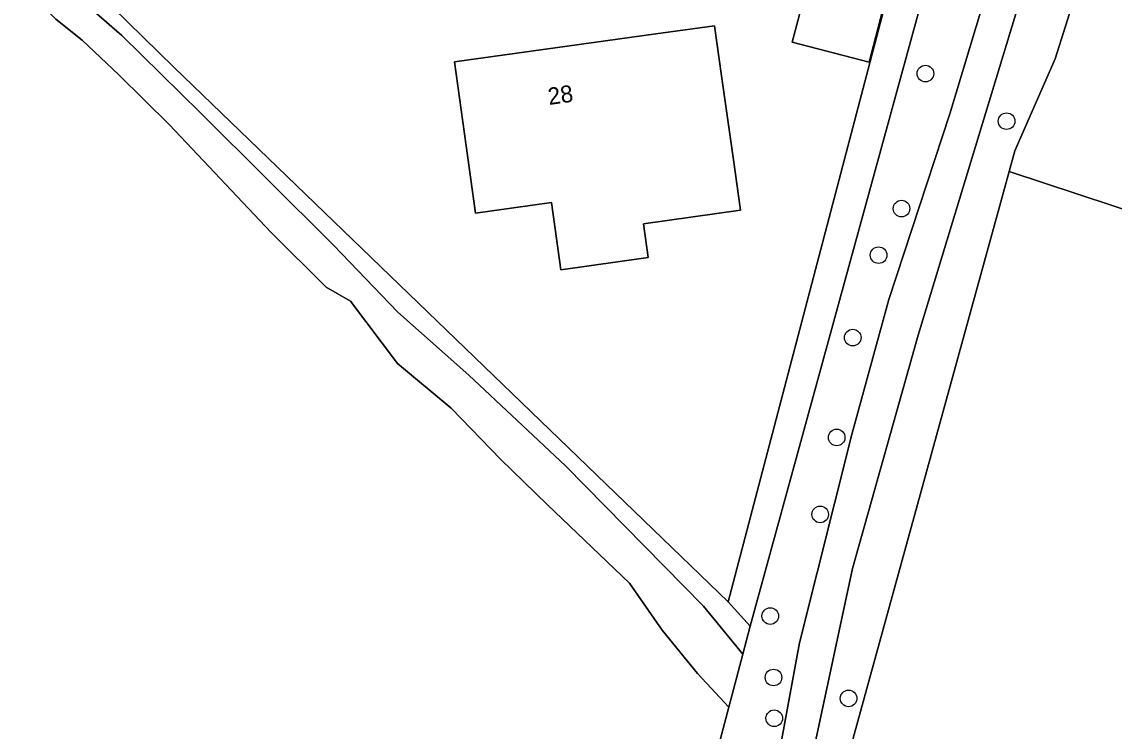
# Model space of a CAD drawing. Extents: x 163426 to 164192, y 380329 to 381641.
# Drawn here: x 163603.5 to 163667.9, y 380813.6 to 380855.4 of the extents above; entities that cross this region are included whole.
import ezdxf

# ---------------------------------------------------------------- set-up
doc = ezdxf.new("R2010")
doc.units = 0
for name, color, linetype in [('IMGEO_Boom', 7, 'Continuous'), ('IMGEO_Erf', 7, 'Continuous'), ('IMGEO_Gemengd_bos', 7, 'Continuous'), ('IMGEO_Grasland_agrarisch', 7, 'Continuous'), ('IMGEO_Grasland_overig', 7, 'Continuous'), ('IMGEO_Groenvoorziening', 7, 'Continuous'), ('IMGEO_Hek', 7, 'Continuous'), ('IMGEO_Loofbos', 7, 'Continuous'), ('IMGEO_Pand', 7, 'Continuous'), ('IMGEO_Pand_nummerreeks', 7, 'Continuous'), ('IMGEO_Waterloop', 7, 'Continuous')]:
    doc.layers.add(name, color=color, linetype=linetype)

msp = doc.modelspace()

# ---------------------------------------------------------------- linework, layer by layer
at = {"layer": 'IMGEO_Boom'}
for centre in [(163656.778, 380852.335), (163661.565, 380849.528), (163655.372, 380844.377), (163654.021, 380841.631), (163652.496, 380836.769), (163651.55, 380830.884), (163650.578, 380826.349), (163647.636, 380820.354), (163647.826, 380816.734), (163652.25, 380815.501), (163647.868, 380814.333)]:
    msp.add_circle(centre, 0.489, dxfattribs=at)
at = {"layer": 'IMGEO_Erf'}
msp.add_lwpolyline([(163597.048, 380867.792), (163612.499, 380852.69), (163645.162, 380821.2), (163654.629, 380857.255), (163667.709, 380905.63), (163629.171, 380905.22), (163627.128, 380902.637)], dxfattribs=at)
for points in [[(163648.932, 380854.186), (163649.868, 380857.757), (163654.396, 380856.57), (163653.46, 380852.998)], [(163629.017, 380853.016), (163640.897, 380854.673), (163644.348, 380855.154), (163644.764, 380852.192), (163645.459, 380847.241), (163645.874, 380844.283), (163640.161, 380843.481), (163640.44, 380841.488), (163635.289, 380840.77), (163634.737, 380844.735), (163630.263, 380844.107), (163629.709, 380848.065)]]:
    msp.add_lwpolyline(points, close=True, dxfattribs=at)
at = {"layer": 'IMGEO_Gemengd_bos'}
for points in [[(163602.738, 380860.396), (163609.418, 380854.587), (163614.054, 380850.017), (163621.912, 380842.205), (163625.678, 380838.261), (163629.868, 380834.565), (163635.57, 380829.219), (163643.702, 380820.94), (163646.008, 380818.103), (163646.446, 380819.754), (163645.162, 380821.2), (163612.499, 380852.69), (163597.048, 380867.792)], [(163619.82, 380719.408), (163645.183, 380814.995), (163643.353, 380816.972), (163641.26, 380819.533), (163639.339, 380822.289), (163634.482, 380826.938), (163631.76, 380829.576), (163628.827, 380832.617), (163625.655, 380835.238), (163622.895, 380838.922), (163621.453, 380839.736), (163618.19, 380842.987), (163612.223, 380849.313), (163609.244, 380852.254), (163607.079, 380854.299), (163605.519, 380855.538), (163604.347, 380856.748), (163602.744, 380858.087)]]:
    msp.add_lwpolyline(points, dxfattribs=at)
at = {"layer": 'IMGEO_Grasland_agrarisch'}
for points in [[(163676.264, 380898.045), (163675.27, 380889.844), (163667.465, 380862.856), (163664.422, 380853.199), (163662.044, 380847.771), (163661.716, 380846.556), (163676.005, 380841.844), (163676.462, 380842.87), (163748.427, 380818.406), (163755.62, 380815.986), (163761.554, 380817.017), (163766.727, 380817.487), (163833.925, 380793.969), (163867.865, 380782.001), (163873.131, 380796.014), (163883.232, 380827.402), (163866.167, 380833.488), (163807.958, 380854.39), (163721.682, 380886.947), (163719.308, 380891.611), (163718.75, 380896.634), (163719.387, 380902.701), (163678.485, 380902.522)], [(163859.158, 380750), (163865.095, 380767.741), (163865.656, 380769.419), (163863.854, 380770.016), (163805.432, 380789.353), (163760.734, 380807.172), (163754.358, 380812.453), (163675.469, 380840.645), (163676.005, 380841.844), (163661.716, 380846.556), (163661.389, 380845.348), (163652.577, 380813.365), (163645.706, 380787.253), (163672.1, 380780.155), (163739.496, 380755.549)]]:
    msp.add_lwpolyline(points, dxfattribs=at)
at = {"layer": 'IMGEO_Grasland_overig'}
for points in [[(163650.263, 380812.779), (163652.48, 380823.169), (163656.357, 380836.919), (163664.656, 380864.293), (163675.415, 380905.712), (163673.232, 380905.689), (163669.497, 380891.125), (163665.164, 380875.29), (163662.078, 380862.748), (163658.213, 380849.959), (163654.619, 380839.009), (163652.469, 380831.14), (163649.361, 380818.786), (163646.727, 380804.476), (163645.538, 380800.753), (163641.29, 380789.931), (163640.039, 380785.25), (163637.312, 380772.479), (163633.485, 380759.624), (163632.057, 380753.224), (163631.159, 380750), (163626.738, 380734.127), (163623.75, 380724.076), (163622.255, 380719.616)], [(163722.383, 380903.697), (163722.338, 380906.17), (163682.307, 380905.781), (163677.393, 380905.733), (163675.415, 380905.712), (163664.656, 380864.293), (163656.357, 380836.919), (163652.48, 380823.169), (163650.263, 380812.779), (163649.012, 380805.413), (163648.047, 380801.938), (163644.743, 380793.389), (163643.102, 380788.541), (163642.446, 380786.186), (163639.087, 380771.729), (163634.937, 380756.516)], [(163661.389, 380845.348), (163661.716, 380846.556), (163662.044, 380847.771), (163664.422, 380853.199), (163667.465, 380862.856), (163675.27, 380889.844), (163676.264, 380898.045)], [(163626.063, 380712.609), (163645.706, 380787.253), (163652.577, 380813.365), (163661.389, 380845.348)]]:
    msp.add_lwpolyline(points, dxfattribs=at)
at = {"layer": 'IMGEO_Groenvoorziening'}
msp.add_lwpolyline([(163646.446, 380819.754), (163656.587, 380856.744), (163669.843, 380905.653), (163667.709, 380905.63), (163654.629, 380857.255), (163645.162, 380821.2)], close=True, dxfattribs=at)
at = {"layer": 'IMGEO_Hek'}
for points in [[(163667.709, 380905.63), (163654.629, 380857.255), (163645.162, 380821.2)], [(163645.162, 380821.2), (163612.499, 380852.69), (163597.048, 380867.792)]]:
    msp.add_lwpolyline(points, dxfattribs=at)
at = {"layer": 'IMGEO_Loofbos'}
for points in [[(163649.361, 380818.786), (163652.469, 380831.14), (163654.619, 380839.009), (163658.213, 380849.959), (163662.078, 380862.748), (163665.164, 380875.29), (163669.497, 380891.125), (163673.232, 380905.689), (163669.843, 380905.653), (163656.587, 380856.744), (163646.446, 380819.754), (163646.008, 380818.103), (163645.183, 380814.995), (163619.82, 380719.408), (163619.266, 380717.321)], [(163622.255, 380719.616), (163623.75, 380724.076), (163626.738, 380734.127), (163631.159, 380750), (163632.057, 380753.224), (163633.485, 380759.624), (163637.312, 380772.479), (163640.039, 380785.25), (163641.29, 380789.931), (163645.538, 380800.753), (163646.727, 380804.476), (163649.361, 380818.786)]]:
    msp.add_lwpolyline(points, dxfattribs=at)
at = {"layer": 'IMGEO_Pand'}
for points in [[(163648.932, 380854.186), (163653.46, 380852.998), (163654.396, 380856.57), (163649.868, 380857.757)], [(163644.764, 380852.192), (163644.348, 380855.154), (163640.897, 380854.673), (163629.017, 380853.016), (163629.709, 380848.065), (163630.263, 380844.107), (163634.737, 380844.735), (163635.289, 380840.77), (163640.44, 380841.488), (163640.161, 380843.481), (163645.874, 380844.283), (163645.459, 380847.241)]]:
    msp.add_lwpolyline(points, close=True, dxfattribs=at)
at = {"layer": 'IMGEO_Waterloop'}
msp.add_lwpolyline([(163605.519, 380855.538), (163607.079, 380854.299), (163609.244, 380852.254), (163612.223, 380849.313), (163618.19, 380842.987), (163621.453, 380839.736), (163622.895, 380838.922), (163625.655, 380835.238), (163628.827, 380832.617), (163631.76, 380829.576), (163634.482, 380826.938), (163639.339, 380822.289), (163641.26, 380819.533), (163643.353, 380816.972), (163645.183, 380814.995), (163646.008, 380818.103), (163643.702, 380820.94), (163635.57, 380829.219), (163629.868, 380834.565), (163625.678, 380838.261), (163621.912, 380842.205), (163614.054, 380850.017), (163609.418, 380854.587), (163602.738, 380860.396)], dxfattribs=at)

# ---------------------------------------------------------------- texts
at = {"layer": 'IMGEO_Pand_nummerreeks'}
msp.add_text('28', height=1, rotation=7.94028, dxfattribs=at).set_placement((163634.595, 380850.482))

doc.saveas('drawing.dxf')
